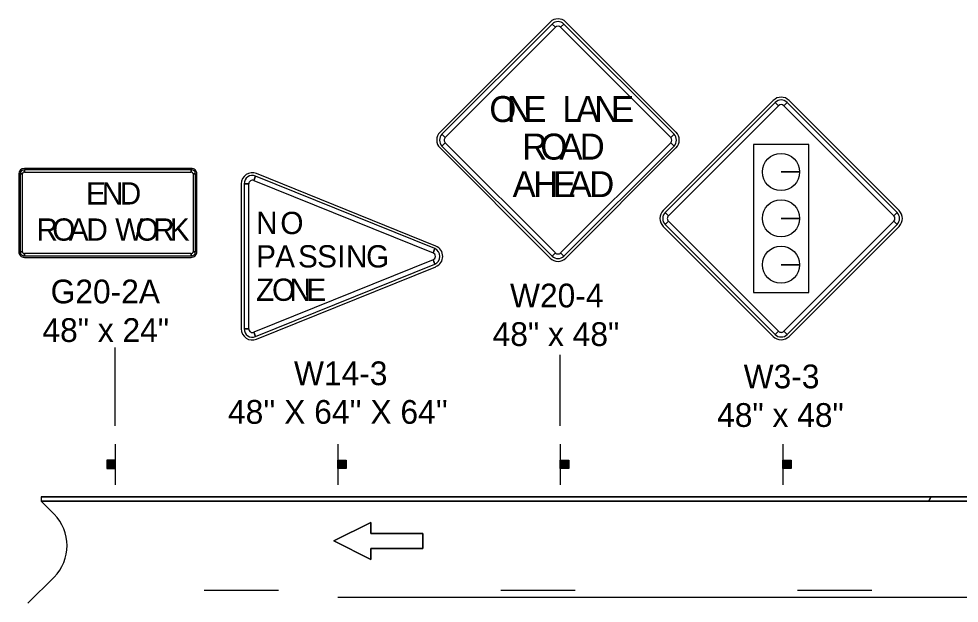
# Model space of a CAD drawing. Extents: x 10133 to 81668, y 4692 to 11018.
# Drawn here: x 20968 to 21602, y 6856 to 7250 of the extents above; entities that cross this region are included whole.
import ezdxf

# ---------------------------------------------------------------- set-up
doc = ezdxf.new("R2010")
doc.units = 0
for name, color, linetype in [('dsnCellElements', 7, 'Continuous'), ('dsnTextTabulation', 7, 'Continuous'), ('SheetAddendum', 7, 'Continuous')]:
    doc.layers.add(name, color=color, linetype=linetype)

msp = doc.modelspace()

# ---------------------------------------------------------------- linework, layer by layer
at = {"layer": 'dsnCellElements'}
for p, q in [((21032.53, 6975.47), (21032.53, 7028.34)), ((21332.53, 6975.47), (21332.53, 7023.42)), ((21032.53, 6963.3), (21032.53, 6935.8)), ((21182.53, 6963.3), (21182.53, 6935.8)), ((21332.53, 6963.3), (21332.53, 6935.8)), ((21482.53, 6963.3), (21482.53, 6935.8)), ((21027.2, 6952.44), (21027.2, 6946.86)), ((21027.52, 6946.86), (21027.52, 6952.44)), ((21027.75, 6952.44), (21027.75, 6946.86)), ((21028.06, 6946.86), (21028.06, 6952.44)), ((21028.29, 6952.44), (21028.27, 6946.86)), ((21028.7, 6946.86), (21028.72, 6952.44)), ((21028.93, 6952.44), (21028.93, 6946.86)), ((21029.36, 6946.86), (21029.36, 6952.44)), ((21029.73, 6952.44), (21029.73, 6946.86)), ((21030.05, 6946.86), (21030.07, 6952.44)), ((21030.28, 6952.44), (21030.28, 6946.86)), ((21030.54, 6946.86), (21030.54, 6952.44)), ((21030.88, 6952.44), (21030.88, 6946.86)), ((21031.08, 6946.86), (21031.08, 6952.44)), ((21031.31, 6952.44), (21031.31, 6946.86)), ((21031.57, 6946.86), (21031.57, 6952.44)), ((21031.83, 6952.44), (21031.83, 6946.86)), ((21032.11, 6946.86), (21032.11, 6952.44)), ((21182.94, 6946.86), (21182.94, 6952.44)), ((21183.22, 6952.44), (21183.22, 6946.86)), ((21183.48, 6946.86), (21183.48, 6952.44)), ((21183.75, 6952.44), (21183.75, 6946.86)), ((21183.97, 6946.86), (21183.97, 6952.44)), ((21184.18, 6952.44), (21184.18, 6946.86)), ((21184.52, 6946.86), (21184.52, 6952.44)), ((21184.78, 6952.44), (21184.78, 6946.86)), ((21185, 6946.86), (21184.98, 6952.44)), ((21185.32, 6952.44), (21185.32, 6946.86)), ((21185.7, 6946.86), (21185.7, 6952.44)), ((21186.13, 6952.44), (21186.13, 6946.86)), ((21186.35, 6946.86), (21186.33, 6952.44)), ((21186.77, 6952.44), (21186.78, 6946.86)), ((21186.99, 6946.86), (21186.99, 6952.44)), ((21187.31, 6952.44), (21187.31, 6946.86)), ((21187.53, 6946.86), (21187.53, 6952.44)), ((21187.85, 6952.44), (21187.85, 6946.86)), ((21332.94, 6946.86), (21332.94, 6952.44)), ((21333.22, 6952.44), (21333.22, 6946.86)), ((21333.48, 6946.86), (21333.48, 6952.44)), ((21333.75, 6952.44), (21333.75, 6946.86)), ((21333.97, 6946.86), (21333.97, 6952.44)), ((21334.18, 6952.44), (21334.18, 6946.86)), ((21334.52, 6946.86), (21334.52, 6952.44)), ((21334.78, 6952.44), (21334.78, 6946.86)), ((21335, 6946.86), (21334.98, 6952.44)), ((21335.32, 6952.44), (21335.32, 6946.86)), ((21335.7, 6946.86), (21335.7, 6952.44)), ((21336.13, 6952.44), (21336.13, 6946.86)), ((21336.35, 6946.86), (21336.33, 6952.44)), ((21336.77, 6952.44), (21336.78, 6946.86)), ((21336.99, 6946.86), (21336.99, 6952.44)), ((21337.31, 6952.44), (21337.31, 6946.86)), ((21337.53, 6946.86), (21337.53, 6952.44)), ((21337.85, 6952.44), (21337.85, 6946.86)), ((21482.94, 6946.86), (21482.94, 6952.44)), ((21483.22, 6952.44), (21483.22, 6946.86)), ((21483.48, 6946.86), (21483.48, 6952.44)), ((21483.75, 6952.44), (21483.75, 6946.86)), ((21483.97, 6946.86), (21483.97, 6952.44)), ((21484.18, 6952.44), (21484.18, 6946.86)), ((21484.52, 6946.86), (21484.52, 6952.44)), ((21484.78, 6952.44), (21484.78, 6946.86)), ((21485, 6946.86), (21484.98, 6952.44)), ((21485.32, 6952.44), (21485.32, 6946.86)), ((21485.7, 6946.86), (21485.7, 6952.44)), ((21486.13, 6952.44), (21486.13, 6946.86)), ((21486.35, 6946.86), (21486.33, 6952.44)), ((21486.77, 6952.44), (21486.78, 6946.86)), ((21486.99, 6946.86), (21486.99, 6952.44)), ((21487.31, 6952.44), (21487.31, 6946.86)), ((21487.53, 6946.86), (21487.53, 6952.44)), ((21487.85, 6952.44), (21487.85, 6946.86)), ((20982.53, 6927.8), (20982.53, 6924.8)), ((20991.31, 6916.02), (20982.53, 6924.8)), ((22292.53, 6924.8), (20982.53, 6924.8)), ((20982.53, 6924.8), (20991.31, 6916.02)), ((20973.74, 6856.02), (20991.31, 6873.59)), ((20991.31, 6873.59), (20973.74, 6856.02))]:
    msp.add_line(p, q, dxfattribs=at)
for points in [[(21032.43, 6946.86), (21032.43, 6952.48), (21026.81, 6952.48), (21026.81, 6946.86)], [(21182.62, 6946.86), (21182.62, 6952.48), (21188.25, 6952.48), (21188.25, 6946.86)], [(21332.62, 6946.86), (21332.62, 6952.48), (21338.25, 6952.48), (21338.25, 6946.86)], [(21482.62, 6946.86), (21482.62, 6952.48), (21488.25, 6952.48), (21488.25, 6946.86)], [(21239.93, 6892.97), (21239.93, 6902.97), (21204.93, 6902.97), (21204.93, 6910.47), (21179.93, 6897.97), (21204.93, 6885.47), (21204.93, 6892.97)]]:
    msp.add_lwpolyline(points, close=True, dxfattribs=at)
msp.add_lwpolyline([(21204.93, 6892.97), (21204.93, 6885.47), (21179.93, 6897.97), (21204.93, 6910.47), (21204.93, 6902.97), (21239.93, 6902.97), (21239.93, 6892.97), (21204.93, 6892.97)], dxfattribs=at)
msp.add_arc((20970.1, 6894.8), 30, 315, 45, dxfattribs=at)
msp.add_arc((20970.1, 6894.8), 30, 315, 45, dxfattribs=at)
at = {"layer": 'dsnTextTabulation'}
for p, q in [((20982.53, 6927.8), (20982.53, 6924.8)), ((21582.3, 6927.8), (20982.53, 6927.8)), ((20982.53, 6924.8), (21581.11, 6924.8)), ((21582.3, 6927.8), (21581.11, 6924.8)), ((21581.11, 6924.8), (21582.3, 6927.8)), ((21581.11, 6924.8), (21627.53, 6924.8)), ((21627.53, 6927.8), (21582.3, 6927.8)), ((21092.53, 6864.8), (21142.53, 6864.8)), ((21632.53, 6859.8), (21182.53, 6859.8)), ((21292.53, 6864.8), (21292.53, 6864.8)), ((21292.53, 6864.8), (21342.53, 6864.8)), ((21492.53, 6864.8), (21492.53, 6864.8)), ((21492.53, 6864.8), (21542.53, 6864.8))]:
    msp.add_line(p, q, dxfattribs=at)
for points in [[(20982.53, 6927.8), (22292.53, 6927.8)], [(20982.53, 6924.8), (22292.53, 6924.8)]]:
    msp.add_lwpolyline(points, dxfattribs=at)
at = {"layer": 'SheetAddendum'}
for p, q in [((21325.76, 7247.65), (21251.51, 7173.41)), ((21410.61, 7173.41), (21336.37, 7247.65)), ((21327.09, 7246.33), (21329.3, 7244.12)), ((21332.83, 7244.12), (21335.04, 7246.33)), ((21476.2, 7194.84), (21401.95, 7120.59)), ((21477.52, 7193.51), (21479.73, 7191.31)), ((21483.27, 7191.31), (21485.48, 7193.51)), ((21561.05, 7120.59), (21486.8, 7194.84)), ((21255.05, 7169.87), (21252.84, 7172.08)), ((21409.29, 7172.08), (21407.08, 7169.87)), ((21252.84, 7164.13), (21255.05, 7166.34)), ((21407.08, 7166.34), (21409.29, 7164.13)), ((21251.51, 7162.8), (21325.76, 7088.55)), ((21336.37, 7088.55), (21410.61, 7162.8)), ((20967.55, 7145.33), (20967.55, 7092.83)), ((20968.49, 7145.33), (20970.05, 7145.33)), ((21083.8, 7149.08), (20971.3, 7149.08)), ((20971.3, 7146.58), (20971.3, 7148.14)), ((21083.8, 7148.14), (21083.8, 7146.58)), ((21085.05, 7145.33), (21086.62, 7145.33)), ((21087.55, 7092.83), (21087.55, 7145.33)), ((21248.7, 7096.72), (21127.87, 7145.59)), ((21493.91, 7146.62), (21481.41, 7146.62)), ((21481.41, 7146.62), (21493.91, 7146.62)), ((21117.56, 7138.64), (21117.56, 7040.89)), ((21119.43, 7138.64), (21122.56, 7138.64)), ((21126, 7140.96), (21127.17, 7143.86)), ((21405.49, 7117.06), (21403.28, 7119.27)), ((21403.28, 7111.31), (21405.49, 7113.52)), ((21493.91, 7115.37), (21481.41, 7115.37)), ((21481.41, 7115.37), (21493.91, 7115.37)), ((21559.72, 7119.27), (21557.51, 7117.06)), ((21557.51, 7113.52), (21559.72, 7111.31)), ((21401.95, 7109.99), (21476.2, 7035.74)), ((21486.8, 7035.74), (21561.05, 7109.99)), ((21247.99, 7094.98), (21246.82, 7092.08)), ((20970.05, 7092.83), (20968.49, 7092.83)), ((20971.3, 7090.02), (20971.3, 7091.58)), ((20971.3, 7089.08), (21083.8, 7089.08)), ((21083.8, 7091.58), (21083.8, 7090.02)), ((21086.62, 7092.83), (21085.05, 7092.83)), ((21329.3, 7092.09), (21327.09, 7089.88)), ((21335.04, 7089.88), (21332.83, 7092.09)), ((21127.87, 7033.94), (21248.7, 7082.81)), ((21246.82, 7087.45), (21247.99, 7084.55)), ((21493.91, 7084.12), (21481.41, 7084.12)), ((21481.41, 7084.12), (21493.91, 7084.12)), ((21122.56, 7040.89), (21119.43, 7040.89)), ((21127.17, 7035.68), (21126, 7038.57)), ((21479.73, 7039.28), (21477.52, 7037.07)), ((21485.48, 7037.07), (21483.27, 7039.28))]:
    msp.add_line(p, q, dxfattribs=at)
for points in [[(21327.09, 7246.33), (21252.84, 7172.08), (21255.05, 7169.87), (21329.3, 7244.12), (21327.09, 7246.33)], [(21409.29, 7172.08), (21335.04, 7246.33), (21332.83, 7244.12), (21407.08, 7169.87), (21409.29, 7172.08)], [(21477.52, 7193.51), (21403.28, 7119.27), (21405.49, 7117.06), (21479.73, 7191.31), (21477.52, 7193.51)], [(21559.72, 7119.27), (21485.48, 7193.51), (21483.27, 7191.31), (21557.51, 7117.06), (21559.72, 7119.27)], [(21252.84, 7164.13), (21327.09, 7089.88), (21329.3, 7092.09), (21255.05, 7166.34), (21252.84, 7164.13)], [(21335.04, 7089.88), (21409.29, 7164.13), (21407.08, 7166.34), (21332.83, 7092.09), (21335.04, 7089.88)], [(21500.23, 7165.24), (21462.77, 7165.24), (21462.77, 7065.35), (21500.23, 7065.35), (21500.23, 7165.24)], [(20968.49, 7145.33), (20968.49, 7092.83), (20970.05, 7092.83), (20970.05, 7145.33), (20968.49, 7145.33)], [(21083.8, 7148.14), (20971.3, 7148.14), (20971.3, 7146.58), (21083.8, 7146.58), (21083.8, 7148.14)], [(21086.62, 7092.83), (21086.62, 7145.33), (21085.05, 7145.33), (21085.05, 7092.83), (21086.62, 7092.83)], [(21119.43, 7138.64), (21119.43, 7040.89), (21122.56, 7040.89), (21122.56, 7138.64), (21119.43, 7138.64)], [(21247.99, 7094.98), (21127.17, 7143.86), (21126, 7140.96), (21246.82, 7092.08), (21247.99, 7094.98)], [(21403.28, 7111.31), (21477.52, 7037.07), (21479.73, 7039.28), (21405.49, 7113.52), (21403.28, 7111.31)], [(21485.48, 7037.07), (21559.72, 7111.31), (21557.51, 7113.52), (21483.27, 7039.28), (21485.48, 7037.07)], [(20971.3, 7090.02), (21083.8, 7090.02), (21083.8, 7091.58), (20971.3, 7091.58), (20971.3, 7090.02)], [(21127.17, 7035.68), (21247.99, 7084.55), (21246.82, 7087.45), (21126, 7038.57), (21127.17, 7035.68)]]:
    msp.add_lwpolyline(points, close=True, dxfattribs=at)
for centre in [(21481.41, 7146.62), (21481.41, 7115.37), (21481.41, 7084.12)]:
    msp.add_circle(centre, 12.5, dxfattribs=at)
for centre, radius, start, end in [((21331.06, 7242.35), 7.5, 44.99999, 134.99974), ((21331.06, 7242.35), 5.62, 44.99999, 134.99974), ((21331.06, 7242.35), 2.5, 44.99999, 134.99974), ((21481.5, 7189.54), 7.5, 44.99999, 134.99974), ((21481.5, 7189.54), 5.62, 44.99999, 134.99974), ((21481.5, 7189.54), 2.5, 44.99999, 134.99974), ((21256.82, 7168.1), 7.5, 134.99974, 224.99995), ((21256.82, 7168.1), 5.62, 134.99974, 224.99995), ((21405.31, 7168.1), 5.62, 315.00016, 44.9998), ((21405.31, 7168.1), 7.5, 315.00016, 44.9998), ((21256.82, 7168.1), 2.5, 134.99974, 224.99995), ((21405.31, 7168.1), 2.5, 315.00016, 44.9998), ((20971.3, 7145.33), 3.75, 90.00021, 179.99985), ((20971.3, 7145.33), 2.81, 90.00021, 179.99985), ((20971.3, 7145.33), 1.25, 90.00021, 179.99985), ((21083.8, 7145.33), 3.75, 0, 90.00021), ((21083.8, 7145.33), 2.81, 0, 90.00021), ((21083.8, 7145.33), 1.25, 0, 90.00021), ((21125.06, 7138.64), 7.5, 67.97571, 179.99985), ((21125.06, 7138.64), 5.62, 67.97571, 179.99985), ((21125.06, 7138.64), 2.5, 67.97571, 179.99985), ((21407.25, 7115.29), 7.5, 134.99974, 224.99995), ((21555.74, 7115.29), 7.5, 315.00016, 44.9998), ((21407.25, 7115.29), 5.62, 134.99974, 224.99995), ((21407.25, 7115.29), 2.5, 134.99974, 224.99995), ((21555.74, 7115.29), 2.5, 315.00016, 44.9998), ((21555.74, 7115.29), 5.62, 315.00016, 44.9998), ((21245.88, 7089.77), 5.62, 292.02456, 67.97541), ((21245.88, 7089.77), 7.5, 292.02456, 67.97598), ((20971.3, 7092.83), 3.75, 179.99985, 270.00006), ((20971.3, 7092.83), 2.81, 179.99985, 270.00006), ((20971.3, 7092.83), 1.25, 179.99985, 270.00006), ((21083.8, 7092.83), 3.75, 270.00006, 0.00027), ((21083.8, 7092.83), 2.81, 270.00006, 0.00027), ((21083.8, 7092.83), 1.25, 270.00006, 0.00027), ((21245.88, 7089.77), 2.5, 292.02456, 67.97541), ((21331.06, 7093.86), 7.5, 224.99995, 315.00016), ((21331.06, 7093.86), 5.62, 224.99995, 315.00016), ((21331.06, 7093.86), 2.5, 224.99995, 315.00016), ((21125.06, 7040.89), 7.5, 179.99985, 292.02456), ((21125.06, 7040.89), 5.62, 179.99985, 292.02456), ((21125.06, 7040.89), 2.5, 179.99985, 292.02456), ((21481.5, 7041.05), 2.5, 224.99995, 315.00016), ((21481.5, 7041.05), 7.5, 224.99995, 315.00016), ((21481.5, 7041.05), 5.62, 224.99995, 315.00016)]:
    msp.add_arc(centre, radius, start, end, dxfattribs=at)

# ---------------------------------------------------------------- texts
for s, height, p in [('O', 17.5, (21284.78, 7180.29)), ('N', 17.5, (21296.55, 7180.29)), ('E', 17.5, (21307.78, 7180.29)), ('L', 17.5, (21334.03, 7180.29)), ('A', 17.5, (21343.23, 7180.29)), ('N', 17.5, (21355.5, 7180.29)), ('E', 17.5, (21366.72, 7180.29)), ('R', 17.5, (21306.89, 7154.98)), ('O', 17.5, (21319.18, 7154.98)), ('A', 17.5, (21332.01, 7154.98)), ('D', 17.5, (21345.67, 7154.98)), ('A', 17.5, (21300.45, 7129.67)), ('H', 17.5, (21314.31, 7129.67)), ('E', 17.5, (21327.53, 7129.67)), ('A', 17.5, (21338.24, 7129.67)), ('D', 17.5, (21352.11, 7129.67)), ('E', 15, (21012.88, 7124.7)), ('N', 15, (21023.5, 7124.7)), ('D', 15, (21035.59, 7124.7)), ('N', 15, (21127.53, 7104.77)), ('O', 15, (21143.87, 7104.77)), ('R', 15, (20979.42, 7100.33)), ('O', 15, (20990.1, 7100.33)), ('A', 15, (21001.26, 7100.33)), ('D', 15, (21013.11, 7100.33)), ('W', 15, (21032.57, 7100.33)), ('O', 15, (21046.3, 7100.33)), ('R', 15, (21058.07, 7100.33)), ('K', 15, (21069.36, 7100.33)), ('P', 15, (21127.53, 7082.27)), ('A', 15, (21140.42, 7082.27)), ('S', 15, (21155.77, 7082.27)), ('S', 15, (21168.66, 7082.27)), ('I', 15, (21182.26, 7082.27)), ('N', 15, (21188.12, 7082.27)), ('G', 15, (21201.71, 7082.27)), ('G20-2A', 16, (20989.02, 7058.08)), ('Z', 15, (21127.53, 7059.77)), ('O', 15, (21138.26, 7059.77)), ('N', 15, (21150.09, 7059.77)), ('E', 15, (21161.46, 7059.77)), ('W20-4', 16, (21298.7, 7055.36)), ('48" x 24"', 16, (20983.49, 7032.08)), ('48" x 48"', 16, (21287, 7029.36)), ('W14-3', 16, (21153.07, 7002.94)), ('W3-3', 16, (21456.21, 7000.83)), ("48'' X 64'' X 64''", 16, (21108.58, 6976.94)), ('48" x 48"', 16, (21438.33, 6974.83))]:
    msp.add_text(s, height=height, dxfattribs=at).set_placement(p)

doc.saveas('drawing.dxf')
